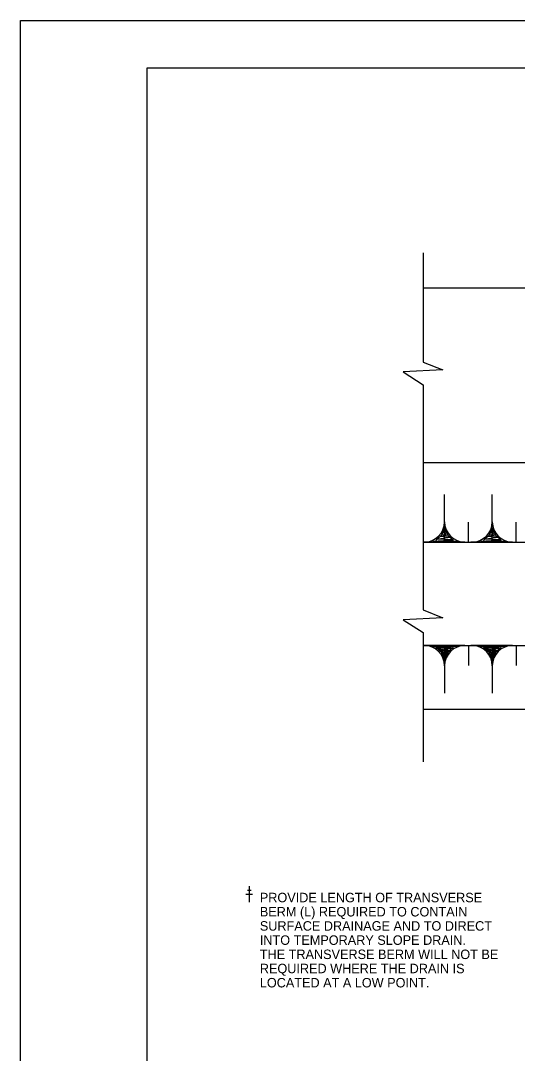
# Model space of a CAD drawing. Extents: x 636462 to 637367, y 299944 to 300538.
# Drawn here: x 636461.9 to 636619.2, y 300211.3 to 300538.4 of the extents above; entities that cross this region are included whole.
import ezdxf

# ---------------------------------------------------------------- set-up
doc = ezdxf.new("R2010")
doc.units = 0
for name, color, linetype in [('1', 7, 'Continuous'), ('Default', 7, 'Continuous'), ('PLT-BNDY', 7, 'Continuous')]:
    doc.layers.add(name, color=color, linetype=linetype)

# ---------------------------------------------------------------- blocks, each defined once
blk = doc.blocks.new('CROSS')
at = {"layer": 'Default'}
for p, q in [((-0.182, 0), (0, 0)), ((-0.096, 0.218), (0, 0.218)), ((0, 0.436), (0, -0.435)), ((0, 0.436), (0, 0)), ((0, 0.218), (0.096, 0.218)), ((0, 0), (0.182, 0))]:
    blk.add_line(p, q, dxfattribs=at)

msp = doc.modelspace()

# ---------------------------------------------------------------- linework, layer by layer
at = {"layer": '1'}
msp.add_lwpolyline([(637287.91, 299959.45), (637287.91, 300523.45), (636501.91, 300523.45), (636501.91, 299959.45), (637287.91, 299959.45), (637287.91, 299985.81), (637087.91, 299985.81), (637087.91, 300050.49), (637287.91, 300050.49), (637287.91, 300079.45), (637087.91, 300079.45), (637087.91, 299959.45), (637166.72, 299959.45), (637166.72, 299985.81), (637166.72, 299959.45), (637243.72, 299959.45), (637243.72, 299985.81), (637243.72, 299973.49), (637287.91, 299973.49)], dxfattribs=at)
at = {"layer": 'Default'}
for p, q in [((636589.35, 300464.94), (636589.35, 300430.32)), ((636589.35, 300453.85), (636841.16, 300453.85)), ((636589.35, 300423.14), (636589.35, 300351.8)), ((636589.35, 300398.45), (636708.58, 300398.45)), ((636596.15, 300373.27), (636596.15, 300388.38)), ((636611.26, 300373.27), (636611.26, 300388.38)), ((636603.7, 300373.27), (636603.7, 300379.56)), ((636618.81, 300373.27), (636618.81, 300379.56)), ((636593.39, 300373.83), (636595.45, 300375.82)), ((636598.91, 300373.83), (636596.86, 300375.82)), ((636608.5, 300373.83), (636610.55, 300375.82)), ((636614.02, 300373.83), (636611.97, 300375.82)), ((636602.59, 300373.27), (636589.35, 300373.27)), ((636589.35, 300373.27), (636589.71, 300373.27)), ((636589.35, 300373.27), (636717.54, 300373.27)), ((636617.7, 300373.27), (636604.46, 300373.27)), ((636604.46, 300373.27), (636604.82, 300373.27)), ((636589.35, 300344.62), (636589.35, 300303.67)), ((636589.35, 300340.53), (636632.71, 300340.53)), ((636602.59, 300340.53), (636589.35, 300340.53)), ((636589.35, 300340.53), (636589.71, 300340.53)), ((636593.39, 300339.97), (636595.44, 300337.98)), ((636596.15, 300340.53), (636596.15, 300325.42)), ((636598.91, 300339.97), (636596.86, 300337.98)), ((636598.91, 300339.97), (636596.86, 300337.98)), ((636603.7, 300340.53), (636603.7, 300334.24)), ((636617.7, 300340.53), (636604.46, 300340.53)), ((636604.46, 300340.53), (636604.82, 300340.53)), ((636608.5, 300339.97), (636610.55, 300337.98)), ((636611.26, 300340.53), (636611.26, 300325.42)), ((636614.02, 300339.97), (636611.96, 300337.98)), ((636614.02, 300339.97), (636611.97, 300337.98)), ((636618.81, 300340.53), (636618.81, 300334.24)), ((636589.35, 300320.39), (636649.03, 300320.39))]:
    msp.add_line(p, q, dxfattribs=at)
for points in [[(636589.35, 300430.32), (636595.57, 300427.83), (636583.07, 300427.22), (636589.35, 300423.14)], [(636599.98, 300373.51), (636592.51, 300373.61), (636598.93, 300374.02), (636593.5, 300374.18), (636597.9, 300374.86), (636594.63, 300375.05), (636597.16, 300375.56), (636596.2, 300377.62), (636595.17, 300375.53), (636596.55, 300375.82), (636596.1, 300376.85), (636595.88, 300376.08)], [(636615.09, 300373.51), (636607.62, 300373.61), (636614.03, 300374.02), (636608.61, 300374.18), (636613.01, 300374.86), (636609.74, 300375.05), (636612.27, 300375.56), (636611.31, 300377.62), (636610.28, 300375.53), (636611.66, 300375.82), (636611.21, 300376.85), (636610.99, 300376.08)], [(636589.35, 300351.8), (636595.57, 300349.31), (636583.07, 300348.7), (636589.35, 300344.62)], [(636592.32, 300340.29), (636599.79, 300340.19), (636593.38, 300339.78), (636598.8, 300339.61), (636594.4, 300338.94), (636597.67, 300338.75), (636595.14, 300338.24), (636596.1, 300336.18), (636597.13, 300338.27), (636595.75, 300337.98), (636596.2, 300336.95), (636596.42, 300337.72)], [(636599.98, 300340.29), (636592.51, 300340.19), (636598.93, 300339.78), (636593.5, 300339.61), (636597.9, 300338.94), (636594.63, 300338.75), (636597.16, 300338.24), (636596.2, 300336.18), (636595.17, 300338.27), (636596.55, 300337.98), (636596.1, 300336.95), (636595.88, 300337.72)], [(636607.43, 300340.29), (636614.9, 300340.19), (636608.48, 300339.78), (636613.91, 300339.61), (636609.51, 300338.94), (636612.78, 300338.75), (636610.25, 300338.24), (636611.21, 300336.18), (636612.24, 300338.27), (636610.86, 300337.98), (636611.31, 300336.95), (636611.53, 300337.72)], [(636615.09, 300340.29), (636607.62, 300340.19), (636614.03, 300339.78), (636608.61, 300339.61), (636613.01, 300338.94), (636609.74, 300338.75), (636612.27, 300338.24), (636611.31, 300336.18), (636610.28, 300338.27), (636611.66, 300337.98), (636611.21, 300336.95), (636610.99, 300337.72)]]:
    msp.add_lwpolyline(points, dxfattribs=at)
for centre, start, end in [((636589.71, 300379.71), 270, 0), ((636589.71, 300379.71), 270, 0), ((636602.59, 300379.71), 180, 270), ((636602.59, 300379.71), 180, 270), ((636604.82, 300379.71), 270, 0), ((636604.82, 300379.71), 270, 0), ((636617.7, 300379.71), 180, 270), ((636617.7, 300379.71), 180, 270), ((636589.71, 300334.09), 0, 90), ((636589.71, 300334.09), 0, 90), ((636602.59, 300334.09), 90, 180), ((636602.59, 300334.09), 90, 180), ((636602.59, 300334.09), 90, 180), ((636604.82, 300334.09), 0, 90), ((636604.82, 300334.09), 0, 90), ((636617.7, 300334.09), 90, 180), ((636617.7, 300334.09), 90, 180), ((636617.7, 300334.09), 90, 180)]:
    msp.add_arc(centre, 6.44, start, end, dxfattribs=at)
at = {"layer": 'PLT-BNDY'}
msp.add_lwpolyline([(636461.91, 300538.45), (637302.91, 300538.45), (637302.91, 299944.45), (636461.91, 299944.45)], close=True, dxfattribs=at)

# ---------------------------------------------------------------- block references
at = {"layer": 'Default', "xscale": 5.777458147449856, "yscale": 5.777458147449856}
msp.add_blockref('CROSS', (636534.32, 300261.77), dxfattribs=at)

# ---------------------------------------------------------------- texts
at = {"layer": 'Default'}
for s, p in [('PROVIDE LENGTH OF TRANSVERSE', (636537.65, 300259.2)), ('BERM (L) REQUIRED TO CONTAIN', (636537.65, 300254.7)), ('SURFACE DRAINAGE AND TO DIRECT', (636537.65, 300250.21)), ('INTO TEMPORARY SLOPE DRAIN.', (636537.65, 300245.71)), ('THE TRANSVERSE BERM WILL NOT BE', (636537.65, 300241.21)), ('REQUIRED WHERE THE DRAIN IS', (636537.65, 300236.72)), ('LOCATED AT A LOW POINT.', (636537.65, 300232.22))]:
    msp.add_text(s, height=2.998, dxfattribs=at).set_placement(p)

doc.saveas('drawing.dxf')
